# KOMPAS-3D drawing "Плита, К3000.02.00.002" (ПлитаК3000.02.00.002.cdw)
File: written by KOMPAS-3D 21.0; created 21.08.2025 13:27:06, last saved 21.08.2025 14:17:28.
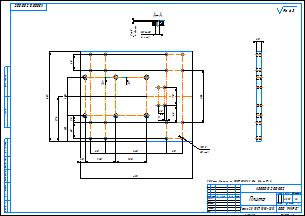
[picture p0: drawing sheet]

Sheet 1: A2, landscape

Document properties: Автор: admin; Полное имя файла: C:\Users\ShavarinML\Desktop\Стапель\2D\ПлитаК3000.02.00.002.cdw; Параметр неуказанной шероховатости: Ra 6,3; Масса: 23.805851

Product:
- Part/product: Плита  | designation К3000.02.00.002
    Материал: Сталь 20кп ГОСТ 1050-2013 (density 7850 kg/m3)
    Масса: 23.805851

Title block, sheet 1: Наименование: Плита; designation: К3000.02.00.002; Материал: Сталь 20 ГОСТ 1050-2013; Масса: 23,81; Количество листов документа: 1; organisation: ООО "МИРО"; Форматы листов документа: A2

Views: Спереди 1, Спереди, Проекционный вид 2, Разрез А-А, Вид:1
Referenced files in C:\Users\ShavarinML\Desktop\Стапель\Задняя бабака\Из трубы\Ролики\: Плита.m3d
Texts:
  Ra 6,3
  К3000.02.00.002 Плита
Dimensions and other numbers on the sheet: 438; 352; 20; 120; 150; 101; 60; 240; 25; 70; 68; 206; 28; 176; 8; 10,5; 20 отв.; -6H; 16; 6 отв.; 2; 6 фасок; 1:2; 1; 23,81

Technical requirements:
  Общие допуски по ГОСТ 30893.1: H14, h14,   IT/2.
